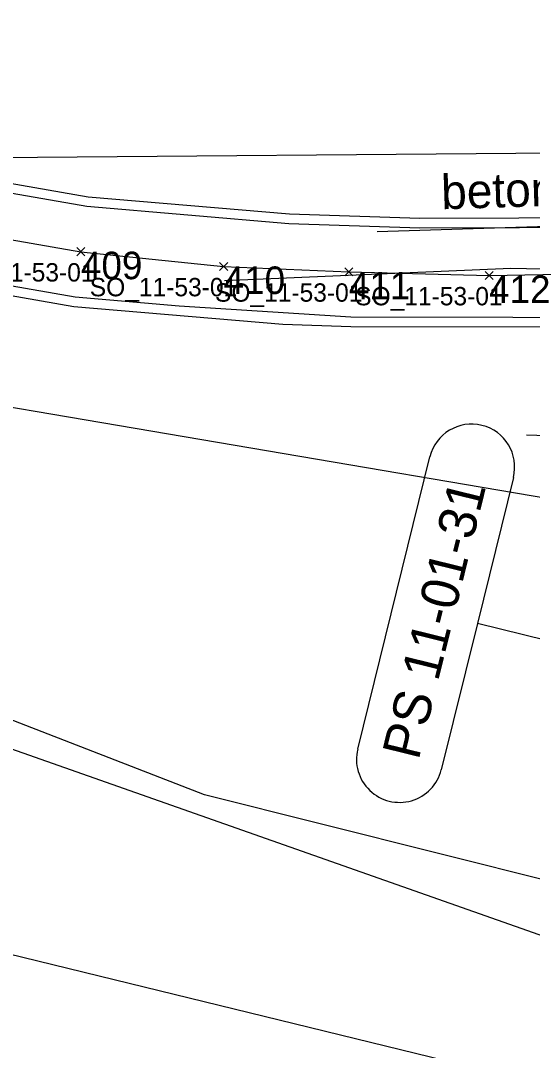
# Model space of a CAD drawing. Extents: x -728800 to -728100, y -1073200 to -1072700.
# Drawn here: x -728539.85 to -728528.71, y -1073041.57 to -1073019.12 of the extents above; entities that cross this region are included whole.
import ezdxf

# ---------------------------------------------------------------- set-up
doc = ezdxf.new("R2010")
doc.units = 0
for name, color, linetype in [('A1_OBVOD Spravy železnic', 7, 'Continuous'), ('A2_OBVOD STAVBY', 7, 'Continuous'), ('B1_body_poloha', 7, 'Continuous'), ('B2_body_číslo', 7, 'Continuous'), ('B3_body_popiska', 7, 'Continuous'), ('B4_Bodové pole', 7, 'Continuous'), ('B6_JŽM', 7, 'Continuous'), ('KOS_kabelová trasa VO', 7, 'Continuous'), ('ZA_02_Dočasný_do_1_roku', 7, 'Continuous'), ('ZZZ_popisky', 7, 'Continuous')]:
    doc.layers.add(name, color=color, linetype=linetype)

msp = doc.modelspace()

# ---------------------------------------------------------------- linework, layer by layer
at = {"layer": 'A1_OBVOD Spravy železnic'}
msp.add_lwpolyline([(-728582.13, -1073004.22), (-728564.68, -1073020.02), (-728543.86, -1073026.9), (-728510.71, -1073032.54), (-728510.22, -1073036.28), (-728509.415, -1073042.185), (-728509.9, -1073046.86), (-728541.12, -1073039.22), (-728572.55, -1073027.78)], dxfattribs=at)
at = {"layer": 'A2_OBVOD STAVBY'}
for points in [[(-728564.164, -1073015.523), (-728556.425, -1073019.431), (-728548.14, -1073022.833), (-728542.882, -1073024.621), (-728538.694, -1073025.349), (-728534.14, -1073025.737), (-728532.664, -1073025.787), (-728522.232, -1073025.806), (-728521.488, -1073028.32), (-728521.545, -1073030.726), (-728521.594, -1073032.788), (-728517.755, -1073032.879), (-728517.209, -1073045.129)], [(-728509.455, -1073035.234), (-728510.689, -1073028.502), (-728511.933, -1073022.707), (-728511.986, -1073020.002), (-728513.157, -1073020.217), (-728515.255, -1073019.379), (-728517.216, -1073018.59), (-728517.096, -1073019.442), (-728517.727, -1073020.685), (-728519.2, -1073021.56), (-728519.78, -1073021.597), (-728522.531, -1073023.408), (-728531.159, -1073023.437), (-728533.997, -1073023.341), (-728538.386, -1073022.967), (-728542.291, -1073022.287), (-728547.296, -1073020.586), (-728553.966, -1073017.86)]]:
    msp.add_lwpolyline(points, dxfattribs=at)
at = {"layer": 'B1_body_poloha'}
for p, q in [((-728538.628, -1073024.07), (-728538.452, -1073024.246)), ((-728538.628, -1073024.246), (-728538.452, -1073024.07)), ((-728535.52, -1073024.392), (-728535.344, -1073024.568)), ((-728535.52, -1073024.568), (-728535.344, -1073024.392)), ((-728532.793, -1073024.51), (-728532.617, -1073024.686)), ((-728532.793, -1073024.686), (-728532.617, -1073024.51)), ((-728529.739, -1073024.589), (-728529.563, -1073024.765)), ((-728529.739, -1073024.765), (-728529.563, -1073024.589))]:
    msp.add_line(p, q, dxfattribs=at)
at = {"layer": 'B2_body_číslo'}
for p, q in [((-728538.54, -1073024.158), (-728538.54, -1073024.158)), ((-728535.432, -1073024.48), (-728535.432, -1073024.48)), ((-728532.705, -1073024.598), (-728532.705, -1073024.598)), ((-728529.651, -1073024.677), (-728529.651, -1073024.677))]:
    msp.add_line(p, q, dxfattribs=at)
at = {"layer": 'B4_Bodové pole'}
msp.add_lwpolyline([(-728665.963, -1072915.444), (-728594.709, -1073015.734), (-728502.086, -1073048.369), (-728347.458, -1073023.537)], dxfattribs=at)
at = {"layer": 'B6_JŽM'}
msp.add_line((-728522.835, -1073021.968), (-728542.221, -1073022.127), dxfattribs=at)
for points in [[(-728300.809, -1073024.355), (-728320.8, -1073026.914), (-728374.008, -1073033.722), (-728429.095, -1073040.747), (-728461.932, -1073044.273), (-728481.199, -1073044.815), (-728499.353, -1073043.648), (-728506.01, -1073042.737), (-728514.574, -1073041.329), (-728535.848, -1073035.998), (-728561.353, -1073026.113), (-728583.963, -1073013.524), (-728603.757, -1072998.891), (-728619.185, -1072984.418), (-728634.193, -1072966.825), (-728646.078, -1072949.194), (-728656.182, -1072930.072), (-728664.987, -1072910.227), (-728668.627, -1072901.808), (-728681.252, -1072876.016), (-728691.886, -1072859.663)], [(-728535.414, -1073024.787), (-728529.18, -1073024.517), (-728519.218, -1073024.728), (-728515.346, -1073023.472), (-728514.359, -1073023.043), (-728513.624, -1073022.497), (-728513.279, -1073022.092), (-728513.109, -1073021.591), (-728513.091, -1073020.945), (-728514.696, -1073012.189)], [(-728532.088, -1073023.721), (-728519.526, -1073023.322), (-728519.714, -1073021.793), (-728522.835, -1073021.968)], [(-728510.066, -1073037.464), (-728511.097, -1073030.537), (-728511.871, -1073029.55), (-728512.902, -1073029.227), (-728513.865, -1073029.238), (-728518.889, -1073028.771), (-728523.455, -1073028.329), (-728528.834, -1073028.159)]]:
    msp.add_lwpolyline(points, dxfattribs=at)
at = {"layer": 'KOS_kabelová trasa VO'}
msp.add_lwpolyline([(-728561.457, -1073013.169), (-728562.506, -1073015.027), (-728558.898, -1073016.89), (-728555.929, -1073018.337), (-728552.96, -1073019.584), (-728550.284, -1073020.683), (-728547.718, -1073021.71), (-728545.504, -1073022.477), (-728542.587, -1073023.454), (-728538.54, -1073024.158), (-728535.432, -1073024.48), (-728532.705, -1073024.598), (-728529.651, -1073024.677), (-728525.747, -1073024.604), (-728522.277, -1073024.607), (-728519.905, -1073023.659), (-728515.301, -1073022.774)], dxfattribs=at)
at = {"layer": 'ZA_02_Dočasný_do_1_roku'}
for points in [[(-728542.341, -1073022.482), (-728538.412, -1073023.165), (-728534.009, -1073023.54), (-728531.162, -1073023.637), (-728526.817, -1073023.623), (-728522.471, -1073023.608), (-728519.714, -1073021.793), (-728519.139, -1073021.757), (-728517.575, -1073020.827), (-728516.889, -1073019.476), (-728516.969, -1073018.905), (-728513.177, -1073020.424), (-728512.181, -1073020.241), (-728512.132, -1073022.73), (-728509.606, -1073035.517), (-728510.327, -1073035.465), (-728509.415, -1073042.185)], [(-728517.01, -1073045.12), (-728517.286, -1073038.902), (-728517.563, -1073032.683), (-728521.389, -1073032.592), (-728521.287, -1073028.294), (-728522.083, -1073025.607), (-728532.66, -1073025.587), (-728536.398, -1073025.344), (-728538.668, -1073025.15), (-728542.832, -1073024.426)]]:
    msp.add_lwpolyline(points, dxfattribs=at)
at = {"layer": 'ZZZ_popisky'}
for points in [[(-728532.511, -1073035), (-728530.94, -1073028.628)], [(-728529.12, -1073029.077), (-728529.905, -1073032.263)], [(-728513.758, -1073036.245), (-728529.905, -1073032.263), (-728530.691, -1073035.449)]]:
    msp.add_lwpolyline(points, dxfattribs=at)
for centre, start, end in [((-728530.03, -1073028.853), 346.1462, 166.1462), ((-728531.601, -1073035.224), 166.1462, 346.1462)]:
    msp.add_arc(centre, 0.937, start, end, dxfattribs=at)

# ---------------------------------------------------------------- texts
at = {"layer": 'B2_body_číslo'}
for s, p in [('409', (-728538.54, -1073024.758)), ('410', (-728535.432, -1073025.08)), ('411', (-728532.705, -1073025.198)), ('412', (-728529.651, -1073025.277))]:
    msp.add_text(s, height=0.6, dxfattribs=at).set_placement(p)
at = {"layer": 'B3_body_popiska'}
for p in [(-728541.456, -1073024.808), (-728538.348, -1073025.13), (-728535.621, -1073025.248), (-728532.567, -1073025.327)]:
    msp.add_text('SO_11-53-01', height=0.4, dxfattribs=at).set_placement(p)
at = {"layer": 'B6_JŽM'}
msp.add_text('beton chodnik', height=0.75, rotation=1.8192, dxfattribs=at).set_placement((-728530.683, -1073023.234))
at = {"layer": 'ZZZ_popisky'}
msp.add_text('PS 11-01-31', height=0.82031, rotation=76.1462, dxfattribs=at).set_placement((-728531.188, -1073035.259))

doc.saveas('drawing.dxf')
